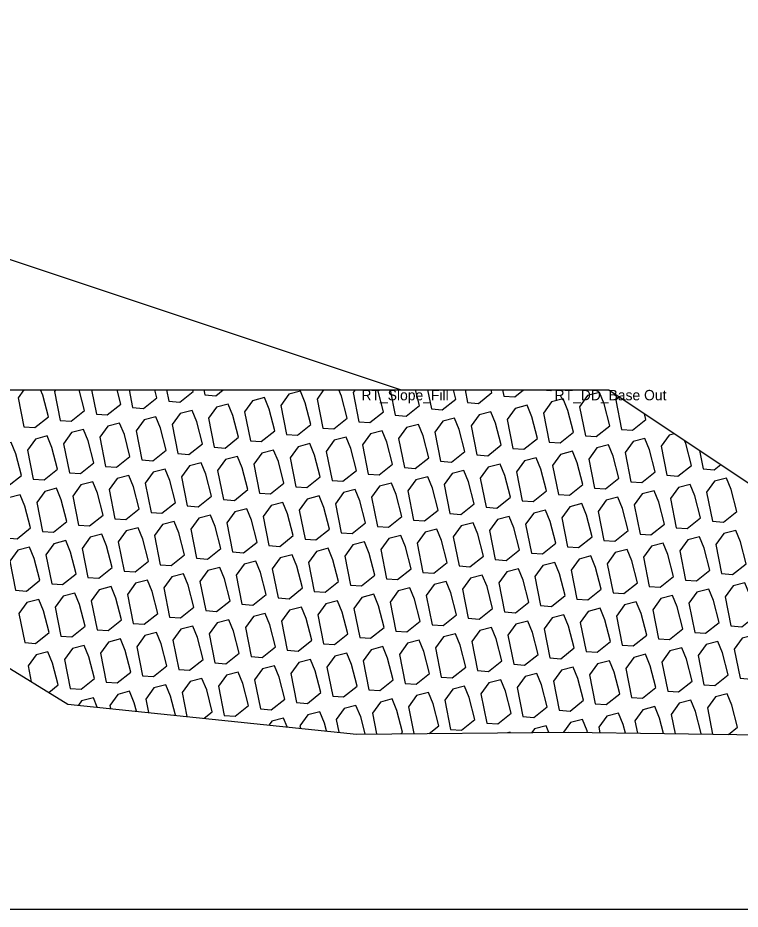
# Model space of a CAD drawing. Extents: x -26 to 203, y -10 to 20020.
# Drawn here: x 127.06 to 134.02, y 16000 to 16008.58 of the extents above; entities that cross this region are included whole.
import ezdxf

# ---------------------------------------------------------------- set-up
doc = ezdxf.new("R2010")
doc.units = 0
for name, color, linetype in [('Default', 7, 'Continuous'), ('Exist Cross Section Cell', 7, 'Continuous'), ('Exist XS Ground Line', 7, 'Continuous'), ('Old_Level_1', 7, 'Continuous'), ('Prop CMT Rip Rap Class II', 7, 'Continuous'), ('Prop CMT Slope Grass', 7, 'Continuous')]:
    doc.layers.add(name, color=color, linetype=linetype)

msp = doc.modelspace()

# ---------------------------------------------------------------- linework, layer by layer
at = {"layer": 'Exist Cross Section Cell'}
msp.add_line((100, 16000), (200, 16000), dxfattribs=at)
at = {"layer": 'Exist XS Ground Line'}
for p, q in [((119.9228, 16006.6301), (127.5406, 16001.9753)), ((127.5406, 16001.9753), (130.3201, 16001.6864)), ((130.3201, 16001.6864), (132.3586, 16001.7032)), ((132.3586, 16001.7032), (148.7075, 16001.4911))]:
    msp.add_line(p, q, dxfattribs=at)
at = {"layer": 'Old_Level_1'}
for p, q in [((127.7692, 16005), (127.8153, 16004.7679)), ((128.13, 16005), (128.1639, 16004.8293)), ((128.4908, 16005), (128.5125, 16004.8908)), ((128.8516, 16005), (128.8611, 16004.9523)), ((130.6444, 16005), (130.6929, 16004.7555)), ((131.0052, 16005), (131.0415, 16004.817)), ((131.366, 16005), (131.3901, 16004.8785)), ((131.7268, 16005), (131.7387, 16004.9399)), ((133.2211, 16004.6862), (133.222, 16004.6817)), ((133.222, 16004.6817), (133.2285, 16004.6813)), ((133.624, 16004.4176), (133.6595, 16004.2391))]:
    msp.add_line(p, q, dxfattribs=at)
for points in [[(127.1168, 16005), (127.0625, 16004.9249), (127.1181, 16004.6449)], [(127.1181, 16004.6449), (127.2233, 16004.6373), (127.3529, 16004.7405), (127.2984, 16004.9511), (127.2783, 16005)], [(127.4209, 16005), (127.4111, 16004.9864), (127.4667, 16004.7064)], [(127.4667, 16004.7064), (127.5719, 16004.6988), (127.7015, 16004.802), (127.6503, 16005)], [(127.8153, 16004.7679), (127.9205, 16004.7602), (128.0501, 16004.8634), (128.0148, 16005)], [(128.1639, 16004.8293), (128.2691, 16004.8217), (128.3987, 16004.9249), (128.3793, 16005)], [(128.5125, 16004.8908), (128.6177, 16004.8832), (128.7473, 16004.9864), (128.7437, 16005)], [(128.8611, 16004.9523), (128.9663, 16004.9446), (129.0358, 16005)], [(130.0034, 16005), (129.9401, 16004.9126), (129.9957, 16004.6326)], [(129.9957, 16004.6326), (130.101, 16004.625), (130.2305, 16004.7282), (130.1761, 16004.9388), (130.1509, 16005)], [(130.3075, 16005), (130.2887, 16004.9741), (130.3443, 16004.6941)], [(130.3443, 16004.6941), (130.4496, 16004.6864), (130.5791, 16004.7896), (130.5247, 16005)], [(130.6929, 16004.7555), (130.7982, 16004.7479), (130.9277, 16004.8511), (130.8892, 16005)], [(131.0415, 16004.817), (131.1468, 16004.8094), (131.2763, 16004.9126), (131.2537, 16005)], [(131.3901, 16004.8785), (131.4954, 16004.8708), (131.6249, 16004.974), (131.6182, 16005)], [(131.7387, 16004.9399), (131.844, 16004.9323), (131.9289, 16005)], [(132.1068, 16005), (132.1926, 16004.9938), (132.2004, 16005)], [(132.8445, 16004.9372), (132.8178, 16004.9003), (132.8734, 16004.6203)], [(132.8734, 16004.6203), (132.9786, 16004.6126), (133.1082, 16004.7158), (133.0939, 16004.771)], [(130.7818, 16004.2515), (130.8871, 16004.2438), (131.0166, 16004.347), (130.9622, 16004.5576), (130.917, 16004.6673), (130.8033, 16004.6379), (130.7262, 16004.5315), (130.7818, 16004.2515)], [(133.3841, 16004.5775), (133.3323, 16004.5641), (133.2553, 16004.4577), (133.3109, 16004.1777)], [(133.3109, 16004.1777), (133.4161, 16004.17), (133.5457, 16004.2732), (133.4912, 16004.4838), (133.4786, 16004.5145)], [(133.6595, 16004.2391), (133.7647, 16004.2315), (133.8278, 16004.2817)], [(131.2193, 16003.8089), (131.3245, 16003.8012), (131.4541, 16003.9044), (131.3996, 16004.115), (131.3545, 16004.2247), (131.2407, 16004.1953), (131.1637, 16004.0889), (131.2193, 16003.8089)], [(131.3082, 16003.3048), (131.4134, 16003.2972), (131.543, 16003.4004), (131.4885, 16003.611), (131.4434, 16003.7206), (131.3296, 16003.6912), (131.2526, 16003.5848), (131.3082, 16003.3048)], [(131.7456, 16002.8622), (131.8509, 16002.8546), (131.9804, 16002.9578), (131.926, 16003.1683), (131.8809, 16003.278), (131.7671, 16003.2486), (131.69, 16003.1422), (131.7456, 16002.8622)], [(131.8345, 16002.3581), (131.9398, 16002.3505), (132.0693, 16002.4537), (132.0149, 16002.6643), (131.9697, 16002.774), (131.856, 16002.7446), (131.7789, 16002.6381), (131.8345, 16002.3581)], [(127.3583, 16002.0867), (127.4487, 16002.1587), (127.3942, 16002.3693), (127.3491, 16002.479), (127.2353, 16002.4496), (127.1583, 16002.3431), (127.1886, 16002.1904)], [(128.8545, 16001.8388), (128.932, 16001.9005), (128.8775, 16002.1111), (128.8324, 16002.2208), (128.7186, 16002.1914), (128.6415, 16002.0849), (128.687, 16001.8562)], [(128.2014, 16001.9067), (128.1803, 16001.9881), (128.1352, 16002.0978), (128.0214, 16002.0684), (127.9443, 16001.962), (127.9502, 16001.9328)], [(128.5759, 16001.8677), (128.5289, 16002.0496), (128.4838, 16002.1593), (128.37, 16002.1299), (128.2929, 16002.0235), (128.3186, 16001.8945)], [(127.8238, 16001.9459), (127.7866, 16002.0364), (127.6728, 16002.007), (127.6423, 16001.9648)], [(130.7464, 16001.6899), (130.7638, 16001.7038), (130.7094, 16001.9143), (130.6642, 16002.024), (130.5505, 16001.9946), (130.4734, 16001.8882), (130.5132, 16001.688)], [(131.0207, 16001.6922), (131.1124, 16001.7652), (131.058, 16001.9758), (131.0128, 16002.0855), (130.8991, 16002.0561), (130.822, 16001.9497), (130.8734, 16001.691)], [(133.6355, 16001.6867), (133.6415, 16001.6914), (133.587, 16001.902), (133.5419, 16002.0117), (133.4281, 16001.9823), (133.3511, 16001.8759), (133.388, 16001.6899)], [(133.9026, 16001.6832), (133.9901, 16001.7529), (133.9356, 16001.9635), (133.8905, 16002.0732), (133.7767, 16002.0438), (133.6997, 16001.9373), (133.7497, 16001.6852)], [(130.4036, 16001.6871), (130.3608, 16001.8529), (130.3156, 16001.9626), (130.2019, 16001.9332), (130.1248, 16001.8267), (130.1492, 16001.7042)], [(133.277, 16001.6913), (133.2384, 16001.8405), (133.1933, 16001.9502), (133.0795, 16001.9208), (133.0025, 16001.8144), (133.0263, 16001.6946)], [(129.653, 16001.7558), (129.6184, 16001.8396), (129.5047, 16001.8102), (129.4784, 16001.7739)], [(130.0316, 16001.7164), (130.0122, 16001.7914), (129.967, 16001.9011), (129.8533, 16001.8717), (129.7762, 16001.7653), (129.7807, 16001.7425)], [(132.9113, 16001.6961), (132.8898, 16001.7791), (132.8447, 16001.8888), (132.7309, 16001.8594), (132.6539, 16001.7529), (132.6645, 16001.6993)], [(132.1739, 16001.7017), (132.1475, 16001.7658), (132.0337, 16001.7364), (132.0076, 16001.7003)], [(132.5456, 16001.7008), (132.5412, 16001.7176), (132.4961, 16001.8273), (132.3823, 16001.7979), (132.3135, 16001.7029)], [(131.8013, 16001.6986), (131.7989, 16001.7044), (131.7759, 16001.6984)]]:
    msp.add_lwpolyline(points, dxfattribs=at)
for points in [[(129.2985, 16004.5097), (129.4038, 16004.502), (129.5333, 16004.6052), (129.4789, 16004.8158), (129.4337, 16004.9255), (129.32, 16004.8961), (129.2429, 16004.7897)], [(129.6471, 16004.5711), (129.7524, 16004.5635), (129.8819, 16004.6667), (129.8275, 16004.8773), (129.7823, 16004.987), (129.6686, 16004.9576), (129.5915, 16004.8511)], [(132.5248, 16004.5588), (132.6301, 16004.5512), (132.7596, 16004.6544), (132.7051, 16004.865), (132.66, 16004.9746), (132.5462, 16004.9452), (132.4692, 16004.8388)], [(128.9499, 16004.4482), (129.0552, 16004.4406), (129.1847, 16004.5438), (129.1303, 16004.7544), (129.0852, 16004.864), (128.9714, 16004.8346), (128.8943, 16004.7282)], [(131.8276, 16004.4359), (131.9329, 16004.4282), (132.0624, 16004.5314), (132.008, 16004.742), (131.9628, 16004.8517), (131.849, 16004.8223), (131.772, 16004.7159)], [(132.1762, 16004.4973), (132.2815, 16004.4897), (132.411, 16004.5929), (132.3565, 16004.8035), (132.3114, 16004.9132), (132.1976, 16004.8838), (132.1206, 16004.7773)], [(128.6013, 16004.3867), (128.7066, 16004.3791), (128.8361, 16004.4823), (128.7817, 16004.6929), (128.7366, 16004.8026), (128.6228, 16004.7732), (128.5457, 16004.6667)], [(131.479, 16004.3744), (131.5843, 16004.3668), (131.7138, 16004.47), (131.6594, 16004.6806), (131.6142, 16004.7902), (131.5005, 16004.7608), (131.4234, 16004.6544)], [(127.9041, 16004.2638), (128.0094, 16004.2562), (128.139, 16004.3594), (128.0845, 16004.57), (128.0394, 16004.6796), (127.9256, 16004.6502), (127.8485, 16004.5438)], [(128.2527, 16004.3253), (128.358, 16004.3176), (128.4875, 16004.4208), (128.4331, 16004.6314), (128.388, 16004.7411), (128.2742, 16004.7117), (128.1971, 16004.6053)], [(131.1304, 16004.3129), (131.2357, 16004.3053), (131.3652, 16004.4085), (131.3108, 16004.6191), (131.2656, 16004.7288), (131.1519, 16004.6994), (131.0748, 16004.5929)], [(127.5556, 16004.2023), (127.6608, 16004.1947), (127.7904, 16004.2979), (127.7359, 16004.5085), (127.6908, 16004.6182), (127.577, 16004.5888), (127.4999, 16004.4823)], [(130.4332, 16004.19), (130.5385, 16004.1824), (130.668, 16004.2856), (130.6136, 16004.4962), (130.5684, 16004.6058), (130.4547, 16004.5764), (130.3776, 16004.47)], [(127.207, 16004.1409), (127.3122, 16004.1332), (127.4418, 16004.2364), (127.3873, 16004.447), (127.3422, 16004.5567), (127.2284, 16004.5273), (127.1513, 16004.4209)], [(130.0846, 16004.1285), (130.1899, 16004.1209), (130.3194, 16004.2241), (130.265, 16004.4347), (130.2198, 16004.5444), (130.1061, 16004.515), (130.029, 16004.4085)], [(132.9623, 16004.1162), (133.0675, 16004.1086), (133.1971, 16004.2118), (133.1426, 16004.4224), (133.0975, 16004.532), (132.9837, 16004.5026), (132.9067, 16004.3962)], [(126.8584, 16004.0794), (126.9636, 16004.0718), (127.0932, 16004.175), (127.0387, 16004.3856), (126.9936, 16004.4952), (126.8798, 16004.4658), (126.8028, 16004.3594)], [(129.3874, 16004.0056), (129.4927, 16003.998), (129.6222, 16004.1012), (129.5678, 16004.3118), (129.5226, 16004.4214), (129.4089, 16004.392), (129.3318, 16004.2856)], [(129.736, 16004.0671), (129.8413, 16004.0594), (129.9708, 16004.1626), (129.9164, 16004.3732), (129.8712, 16004.4829), (129.7575, 16004.4535), (129.6804, 16004.3471)], [(132.6137, 16004.0547), (132.7189, 16004.0471), (132.8485, 16004.1503), (132.794, 16004.3609), (132.7489, 16004.4706), (132.6351, 16004.4412), (132.5581, 16004.3347)], [(129.0388, 16003.9441), (129.1441, 16003.9365), (129.2736, 16004.0397), (129.2192, 16004.2503), (129.174, 16004.36), (129.0603, 16004.3306), (128.9832, 16004.2241)], [(131.9165, 16003.9318), (132.0217, 16003.9242), (132.1513, 16004.0274), (132.0968, 16004.238), (132.0517, 16004.3476), (131.9379, 16004.3182), (131.8609, 16004.2118)], [(132.2651, 16003.9933), (132.3703, 16003.9856), (132.4999, 16004.0888), (132.4454, 16004.2994), (132.4003, 16004.4091), (132.2865, 16004.3797), (132.2095, 16004.2733)], [(128.6902, 16003.8827), (128.7955, 16003.875), (128.925, 16003.9782), (128.8706, 16004.1888), (128.8254, 16004.2985), (128.7117, 16004.2691), (128.6346, 16004.1627)], [(131.5679, 16003.8703), (131.6731, 16003.8627), (131.8027, 16003.9659), (131.7482, 16004.1765), (131.7031, 16004.2862), (131.5893, 16004.2568), (131.5123, 16004.1503)], [(127.993, 16003.7597), (128.0983, 16003.7521), (128.2278, 16003.8553), (128.1734, 16004.0659), (128.1282, 16004.1756), (128.0145, 16004.1462), (127.9374, 16004.0397)], [(128.3416, 16003.8212), (128.4469, 16003.8136), (128.5764, 16003.9168), (128.522, 16004.1274), (128.4768, 16004.237), (128.3631, 16004.2076), (128.286, 16004.1012)], [(130.8707, 16003.7474), (130.9759, 16003.7398), (131.1055, 16003.843), (131.051, 16004.0536), (131.0059, 16004.1632), (130.8921, 16004.1338), (130.8151, 16004.0274)], [(127.6444, 16003.6983), (127.7497, 16003.6906), (127.8792, 16003.7938), (127.8248, 16004.0044), (127.7796, 16004.1141), (127.6659, 16004.0847), (127.5888, 16003.9783)], [(130.5221, 16003.6859), (130.6274, 16003.6783), (130.7569, 16003.7815), (130.7024, 16003.9921), (130.6573, 16004.1018), (130.5435, 16004.0724), (130.4665, 16003.9659)], [(133.3997, 16003.6736), (133.505, 16003.666), (133.6345, 16003.7692), (133.5801, 16003.9798), (133.535, 16004.0894), (133.4212, 16004.06), (133.3441, 16003.9536)], [(133.7483, 16003.7351), (133.8536, 16003.7274), (133.9831, 16003.8306), (133.9287, 16004.0412), (133.8836, 16004.1509), (133.7698, 16004.1215), (133.6927, 16004.0151)], [(126.9472, 16003.5753), (127.0525, 16003.5677), (127.182, 16003.6709), (127.1276, 16003.8815), (127.0825, 16003.9912), (126.9687, 16003.9618), (126.8916, 16003.8553)], [(127.2958, 16003.6368), (127.4011, 16003.6292), (127.5306, 16003.7324), (127.4762, 16003.943), (127.431, 16004.0526), (127.3173, 16004.0232), (127.2402, 16003.9168)], [(130.1735, 16003.6245), (130.2788, 16003.6168), (130.4083, 16003.72), (130.3538, 16003.9306), (130.3087, 16004.0403), (130.1949, 16004.0109), (130.1179, 16003.9045)], [(133.0511, 16003.6121), (133.1564, 16003.6045), (133.2859, 16003.7077), (133.2315, 16003.9183), (133.1864, 16004.028), (133.0726, 16003.9986), (132.9955, 16003.8921)], [(129.4763, 16003.5015), (129.5816, 16003.4939), (129.7111, 16003.5971), (129.6567, 16003.8077), (129.6115, 16003.9174), (129.4978, 16003.888), (129.4207, 16003.7815)], [(129.8249, 16003.563), (129.9302, 16003.5554), (130.0597, 16003.6586), (130.0053, 16003.8692), (129.9601, 16003.9788), (129.8463, 16003.9494), (129.7693, 16003.843)], [(132.354, 16003.4892), (132.4592, 16003.4816), (132.5888, 16003.5848), (132.5343, 16003.7954), (132.4892, 16003.905), (132.3754, 16003.8756), (132.2983, 16003.7692)], [(132.7025, 16003.5507), (132.8078, 16003.543), (132.9374, 16003.6462), (132.8829, 16003.8568), (132.8378, 16003.9665), (132.724, 16003.9371), (132.6469, 16003.8307)], [(129.1277, 16003.4401), (129.233, 16003.4324), (129.3625, 16003.5356), (129.3081, 16003.7462), (129.2629, 16003.8559), (129.1492, 16003.8265), (129.0721, 16003.7201)], [(132.0054, 16003.4277), (132.1106, 16003.4201), (132.2402, 16003.5233), (132.1857, 16003.7339), (132.1406, 16003.8436), (132.0268, 16003.8142), (131.9497, 16003.7077)], [(128.4305, 16003.3171), (128.5358, 16003.3095), (128.6653, 16003.4127), (128.6109, 16003.6233), (128.5657, 16003.733), (128.452, 16003.7036), (128.3749, 16003.5971)], [(128.7791, 16003.3786), (128.8844, 16003.371), (129.0139, 16003.4742), (128.9595, 16003.6847), (128.9143, 16003.7944), (128.8006, 16003.765), (128.7235, 16003.6586)], [(131.6568, 16003.3663), (131.762, 16003.3586), (131.8916, 16003.4618), (131.8371, 16003.6724), (131.792, 16003.7821), (131.6782, 16003.7527), (131.6011, 16003.6463)], [(128.0819, 16003.2557), (128.1872, 16003.248), (128.3167, 16003.3512), (128.2623, 16003.5618), (128.2171, 16003.6715), (128.1034, 16003.6421), (128.0263, 16003.5357)], [(130.9596, 16003.2433), (131.0648, 16003.2357), (131.1944, 16003.3389), (131.1399, 16003.5495), (131.0948, 16003.6592), (130.981, 16003.6298), (130.904, 16003.5233)], [(133.8372, 16003.231), (133.9425, 16003.2234), (134.072, 16003.3266), (134.0176, 16003.5372), (133.9724, 16003.6468), (133.8587, 16003.6174), (133.7816, 16003.511)], [(127.7333, 16003.1942), (127.8386, 16003.1866), (127.9681, 16003.2898), (127.9137, 16003.5003), (127.8685, 16003.61), (127.7548, 16003.5806), (127.6777, 16003.4742)], [(130.611, 16003.1819), (130.7162, 16003.1742), (130.8458, 16003.2774), (130.7913, 16003.488), (130.7462, 16003.5977), (130.6324, 16003.5683), (130.5554, 16003.4619)], [(133.4886, 16003.1695), (133.5939, 16003.1619), (133.7234, 16003.2651), (133.669, 16003.4757), (133.6238, 16003.5854), (133.5101, 16003.556), (133.433, 16003.4495)], [(127.0361, 16003.0713), (127.1414, 16003.0636), (127.2709, 16003.1668), (127.2165, 16003.3774), (127.1713, 16003.4871), (127.0576, 16003.4577), (126.9805, 16003.3513)], [(127.3847, 16003.1327), (127.49, 16003.1251), (127.6195, 16003.2283), (127.5651, 16003.4389), (127.5199, 16003.5486), (127.4062, 16003.5192), (127.3291, 16003.4127)], [(129.9138, 16003.0589), (130.019, 16003.0513), (130.1486, 16003.1545), (130.0941, 16003.3651), (130.049, 16003.4748), (129.9352, 16003.4454), (129.8582, 16003.3389)], [(130.2624, 16003.1204), (130.3676, 16003.1128), (130.4972, 16003.216), (130.4427, 16003.4265), (130.3976, 16003.5362), (130.2838, 16003.5068), (130.2068, 16003.4004)], [(133.14, 16003.1081), (133.2453, 16003.1004), (133.3748, 16003.2036), (133.3204, 16003.4142), (133.2752, 16003.5239), (133.1615, 16003.4945), (133.0844, 16003.3881)], [(129.5652, 16002.9975), (129.6704, 16002.9898), (129.8, 16003.093), (129.7455, 16003.3036), (129.7004, 16003.4133), (129.5866, 16003.3839), (129.5096, 16003.2775)], [(132.4428, 16002.9851), (132.5481, 16002.9775), (132.6776, 16003.0807), (132.6232, 16003.2913), (132.578, 16003.401), (132.4643, 16003.3716), (132.3872, 16003.2651)], [(132.7914, 16003.0466), (132.8967, 16003.039), (133.0262, 16003.1422), (132.9718, 16003.3527), (132.9266, 16003.4624), (132.8129, 16003.433), (132.7358, 16003.3266)], [(129.2166, 16002.936), (129.3218, 16002.9284), (129.4514, 16003.0316), (129.3969, 16003.2421), (129.3518, 16003.3518), (129.238, 16003.3224), (129.161, 16003.216)], [(132.0942, 16002.9237), (132.1995, 16002.916), (132.329, 16003.0192), (132.2746, 16003.2298), (132.2294, 16003.3395), (132.1157, 16003.3101), (132.0386, 16003.2037)], [(128.5194, 16002.8131), (128.6247, 16002.8054), (128.7542, 16002.9086), (128.6997, 16003.1192), (128.6546, 16003.2289), (128.5408, 16003.1995), (128.4638, 16003.0931)], [(128.868, 16002.8745), (128.9733, 16002.8669), (129.1028, 16002.9701), (129.0483, 16003.1807), (129.0032, 16003.2904), (128.8894, 16003.261), (128.8124, 16003.1545)], [(131.397, 16002.8007), (131.5023, 16002.7931), (131.6318, 16002.8963), (131.5774, 16003.1069), (131.5323, 16003.2166), (131.4185, 16003.1872), (131.3414, 16003.0807)], [(128.1708, 16002.7516), (128.2761, 16002.744), (128.4056, 16002.8472), (128.3512, 16003.0577), (128.306, 16003.1674), (128.1922, 16003.138), (128.1152, 16003.0316)], [(131.0484, 16002.7393), (131.1537, 16002.7316), (131.2832, 16002.8348), (131.2288, 16003.0454), (131.1837, 16003.1551), (131.0699, 16003.1257), (130.9928, 16003.0193)], [(133.9261, 16002.7269), (134.0314, 16002.7193), (134.1609, 16002.8225), (134.1065, 16003.0331), (134.0613, 16003.1428), (133.9476, 16003.1134), (133.8705, 16003.0069)], [(127.4736, 16002.6287), (127.5789, 16002.621), (127.7084, 16002.7242), (127.654, 16002.9348), (127.6088, 16003.0445), (127.4951, 16003.0151), (127.418, 16002.9087)], [(127.8222, 16002.6901), (127.9275, 16002.6825), (128.057, 16002.7857), (128.0026, 16002.9963), (127.9574, 16003.106), (127.8436, 16003.0766), (127.7666, 16002.9701)], [(130.6998, 16002.6778), (130.8051, 16002.6702), (130.9347, 16002.7734), (130.8802, 16002.9839), (130.8351, 16003.0936), (130.7213, 16003.0642), (130.6442, 16002.9578)], [(133.5775, 16002.6655), (133.6828, 16002.6578), (133.8123, 16002.761), (133.7579, 16002.9716), (133.7127, 16003.0813), (133.599, 16003.0519), (133.5219, 16002.9455)], [(127.125, 16002.5672), (127.2303, 16002.5596), (127.3598, 16002.6628), (127.3054, 16002.8733), (127.2602, 16002.983), (127.1465, 16002.9536), (127.0694, 16002.8472)], [(130.0027, 16002.5549), (130.1079, 16002.5472), (130.2375, 16002.6504), (130.183, 16002.861), (130.1379, 16002.9707), (130.0241, 16002.9413), (129.947, 16002.8349)], [(130.3513, 16002.6163), (130.4565, 16002.6087), (130.5861, 16002.7119), (130.5316, 16002.9225), (130.4865, 16003.0322), (130.3727, 16003.0028), (130.2956, 16002.8963)], [(132.8803, 16002.5425), (132.9856, 16002.5349), (133.1151, 16002.6381), (133.0607, 16002.8487), (133.0155, 16002.9584), (132.9018, 16002.929), (132.8247, 16002.8225)], [(133.2289, 16002.604), (133.3342, 16002.5964), (133.4637, 16002.6996), (133.4093, 16002.9101), (133.3641, 16003.0198), (133.2504, 16002.9904), (133.1733, 16002.884)], [(129.6541, 16002.4934), (129.7593, 16002.4858), (129.8889, 16002.589), (129.8344, 16002.7995), (129.7893, 16002.9092), (129.6755, 16002.8798), (129.5985, 16002.7734)], [(132.5317, 16002.4811), (132.637, 16002.4734), (132.7665, 16002.5766), (132.7121, 16002.7872), (132.6669, 16002.8969), (132.5532, 16002.8675), (132.4761, 16002.7611)], [(128.9569, 16002.3705), (129.0621, 16002.3628), (129.1917, 16002.466), (129.1372, 16002.6766), (129.0921, 16002.7863), (128.9783, 16002.7569), (128.9013, 16002.6505)], [(129.3055, 16002.4319), (129.4107, 16002.4243), (129.5403, 16002.5275), (129.4858, 16002.7381), (129.4407, 16002.8478), (129.3269, 16002.8184), (129.2499, 16002.7119)], [(132.1831, 16002.4196), (132.2884, 16002.412), (132.4179, 16002.5152), (132.3635, 16002.7257), (132.3183, 16002.8354), (132.2046, 16002.806), (132.1275, 16002.6996)], [(128.6083, 16002.309), (128.7135, 16002.3014), (128.8431, 16002.4046), (128.7886, 16002.6151), (128.7435, 16002.7248), (128.6297, 16002.6954), (128.5527, 16002.589)], [(131.4859, 16002.2967), (131.5912, 16002.289), (131.7207, 16002.3922), (131.6663, 16002.6028), (131.6211, 16002.7125), (131.5074, 16002.6831), (131.4303, 16002.5767)], [(128.2597, 16002.2475), (128.3649, 16002.2399), (128.4945, 16002.3431), (128.44, 16002.5537), (128.3949, 16002.6634), (128.2811, 16002.634), (128.2041, 16002.5275)], [(131.1373, 16002.2352), (131.2426, 16002.2276), (131.3721, 16002.3308), (131.3177, 16002.5413), (131.2725, 16002.651), (131.1588, 16002.6216), (131.0817, 16002.5152)], [(134.015, 16002.2229), (134.1202, 16002.2152), (134.2498, 16002.3184), (134.1953, 16002.529), (134.1502, 16002.6387), (134.0364, 16002.6093), (133.9594, 16002.5029)], [(127.5625, 16002.1246), (127.6677, 16002.117), (127.7973, 16002.2202), (127.7428, 16002.4307), (127.6977, 16002.5404), (127.5839, 16002.511), (127.5069, 16002.4046)], [(127.9111, 16002.1861), (128.0163, 16002.1784), (128.1459, 16002.2816), (128.0914, 16002.4922), (128.0463, 16002.6019), (127.9325, 16002.5725), (127.8555, 16002.4661)], [(130.4401, 16002.1123), (130.5454, 16002.1046), (130.6749, 16002.2078), (130.6205, 16002.4184), (130.5753, 16002.5281), (130.4616, 16002.4987), (130.3845, 16002.3923)], [(130.7887, 16002.1737), (130.894, 16002.1661), (131.0235, 16002.2693), (130.9691, 16002.4799), (130.9239, 16002.5896), (130.8102, 16002.5602), (130.7331, 16002.4537)], [(133.6664, 16002.1614), (133.7716, 16002.1538), (133.9012, 16002.257), (133.8467, 16002.4675), (133.8016, 16002.5772), (133.6878, 16002.5478), (133.6108, 16002.4414)], [(130.0915, 16002.0508), (130.1968, 16002.0432), (130.3263, 16002.1464), (130.2719, 16002.3569), (130.2267, 16002.4666), (130.113, 16002.4372), (130.0359, 16002.3308)], [(132.9692, 16002.0385), (133.0745, 16002.0308), (133.204, 16002.134), (133.1495, 16002.3446), (133.1044, 16002.4543), (132.9906, 16002.4249), (132.9136, 16002.3185)], [(133.3178, 16002.0999), (133.4231, 16002.0923), (133.5526, 16002.1955), (133.4981, 16002.4061), (133.453, 16002.5158), (133.3392, 16002.4864), (133.2622, 16002.3799)], [(129.7429, 16001.9893), (129.8482, 16001.9817), (129.9777, 16002.0849), (129.9233, 16002.2955), (129.8782, 16002.4052), (129.7644, 16002.3758), (129.6873, 16002.2693)], [(132.6206, 16001.977), (132.7259, 16001.9694), (132.8554, 16002.0726), (132.801, 16002.2831), (132.7558, 16002.3928), (132.642, 16002.3634), (132.565, 16002.257)], [(129.0457, 16001.8664), (129.151, 16001.8588), (129.2806, 16001.962), (129.2261, 16002.1725), (129.181, 16002.2822), (129.0672, 16002.2528), (128.9901, 16002.1464)], [(129.3943, 16001.9279), (129.4996, 16001.9202), (129.6291, 16002.0234), (129.5747, 16002.234), (129.5296, 16002.3437), (129.4158, 16002.3143), (129.3387, 16002.2079)], [(131.9234, 16001.8541), (132.0287, 16001.8464), (132.1582, 16001.9496), (132.1038, 16002.1602), (132.0586, 16002.2699), (131.9449, 16002.2405), (131.8678, 16002.1341)], [(132.272, 16001.9155), (132.3773, 16001.9079), (132.5068, 16002.0111), (132.4524, 16002.2217), (132.4072, 16002.3314), (132.2935, 16002.302), (132.2164, 16002.1955)], [(131.5748, 16001.7926), (131.6801, 16001.785), (131.8096, 16001.8882), (131.7552, 16002.0987), (131.71, 16002.2084), (131.5963, 16002.179), (131.5192, 16002.0726)], [(131.2262, 16001.7311), (131.3315, 16001.7235), (131.461, 16001.8267), (131.4066, 16002.0373), (131.3614, 16002.147), (131.2477, 16002.1176), (131.1706, 16002.0111)]]:
    msp.add_lwpolyline(points, close=True, dxfattribs=at)
at = {"layer": 'Prop CMT Rip Rap Class II'}
msp.add_lwpolyline([(122.5906, 16005), (132.7504, 16005), (137.8012, 16001.6326)], dxfattribs=at)
at = {"layer": 'Prop CMT Slope Grass'}
msp.add_lwpolyline([(120, 16008.5831), (130.7504, 16005)], dxfattribs=at)

# ---------------------------------------------------------------- texts
at = {"layer": 'Default'}
for s, p in [('RT_Slope_Fill', (130.3683, 16004.9)), ('RT_DD_Base Out', (132.2279, 16004.9))]:
    msp.add_text(s, height=0.1, dxfattribs=at).set_placement(p)

doc.saveas('drawing.dxf')
